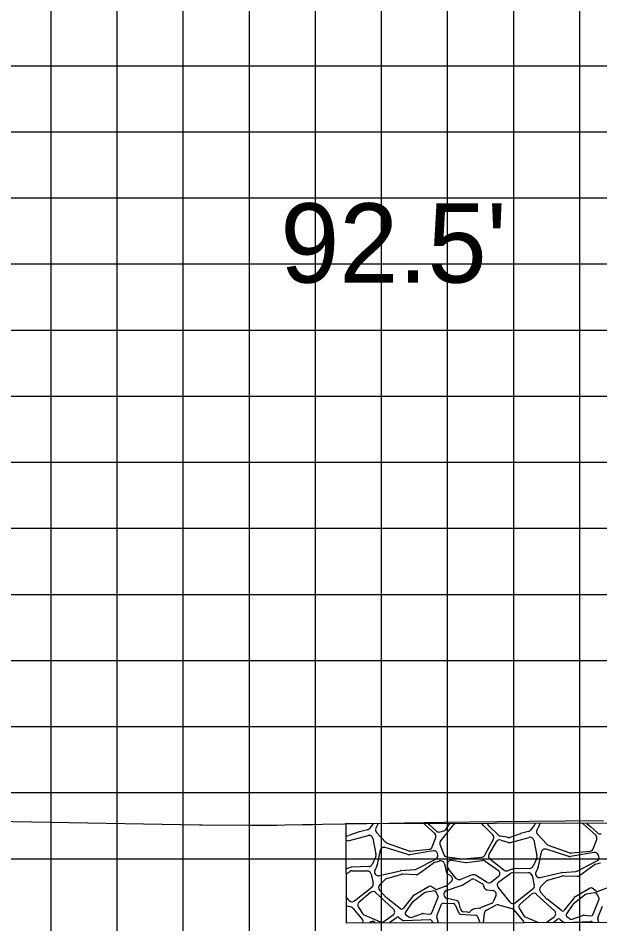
# Model space of a CAD drawing. Extents: x 1785795 to 1786139, y 442591 to 442811.
# Drawn here: x 1785863.55 to 1785872.36, y 442746.68 to 442760.39 of the extents above; entities that cross this region are included whole.
import ezdxf

# ---------------------------------------------------------------- set-up
doc = ezdxf.new("R2010")
doc.units = 0
for name, color, linetype in [('D_Roadway_SlopeLines', 7, 'Continuous'), ('D_Text_Standard', 7, 'Continuous'), ('MAJOR', 7, 'Continuous'), ('MINOR', 7, 'Continuous'), ('S_Roadway_Centerline', 7, 'Continuous')]:
    doc.layers.add(name, color=color, linetype=linetype)

msp = doc.modelspace()

# ---------------------------------------------------------------- linework, layer by layer
at = {"layer": 'D_Roadway_SlopeLines'}
for p, q in [((1785868.921, 442748.188), (1785868.869, 442748.122)), ((1785868.925, 442748.194), (1785868.921, 442748.188)), ((1785868.994, 442748.187), (1785868.967, 442748.125)), ((1785868.997, 442748.194), (1785868.994, 442748.187)), ((1785869.713, 442748.179), (1785869.695, 442748.195)), ((1785869.858, 442748.047), (1785869.713, 442748.179)), ((1785869.758, 442748.195), (1785869.777, 442748.179)), ((1785869.777, 442748.179), (1785869.884, 442748.082)), ((1785870.119, 442748.157), (1785869.945, 442747.938)), ((1785870.024, 442748.108), (1785870.07, 442748.175)), ((1785870.07, 442748.175), (1785870.085, 442748.196)), ((1785870.138, 442748.174), (1785870.129, 442748.167)), ((1785870.166, 442748.196), (1785870.138, 442748.174)), ((1785870.596, 442748.169), (1785870.569, 442748.197)), ((1785870.735, 442748.028), (1785870.596, 442748.169)), ((1785870.821, 442748.022), (1785870.675, 442748.161)), ((1785871.358, 442748.161), (1785871.306, 442748.095)), ((1785871.374, 442748.18), (1785871.358, 442748.161)), ((1785871.431, 442748.16), (1785871.404, 442748.097)), ((1785871.449, 442748.199), (1785871.431, 442748.16)), ((1785872.15, 442748.152), (1785872.097, 442748.2)), ((1785872.295, 442748.019), (1785872.15, 442748.152)), ((1785872.159, 442748.2), (1785872.214, 442748.151)), ((1785872.214, 442748.151), (1785872.322, 442748.055)), ((1785868.526, 442748.013), (1785868.512, 442748.016)), ((1785868.716, 442748.071), (1785868.555, 442748.015)), ((1785868.568, 442747.939), (1785868.848, 442748.016)), ((1785868.838, 442748.103), (1785868.72, 442748.072)), ((1785868.977, 442748.063), (1785869.116, 442747.913)), ((1785869.938, 442748.07), (1785869.993, 442748.086)), ((1785870.947, 442747.989), (1785870.85, 442748.007)), ((1785870.963, 442747.986), (1785870.947, 442747.989)), ((1785871.153, 442748.043), (1785870.992, 442747.988)), ((1785871.005, 442747.912), (1785871.285, 442747.988)), ((1785871.275, 442748.076), (1785871.157, 442748.045)), ((1785871.414, 442748.035), (1785871.553, 442747.886)), ((1785868.512, 442747.947), (1785868.537, 442747.939)), ((1785868.919, 442747.972), (1785868.968, 442747.734)), ((1785869.138, 442747.898), (1785869.464, 442747.782)), ((1785869.82, 442747.845), (1785869.873, 442747.985)), ((1785869.936, 442747.883), (1785869.993, 442747.731)), ((1785870.617, 442747.719), (1785870.745, 442747.961)), ((1785870.679, 442747.734), (1785870.791, 442747.922)), ((1785870.856, 442747.947), (1785870.946, 442747.92)), ((1785870.946, 442747.92), (1785870.974, 442747.912)), ((1785871.356, 442747.945), (1785871.405, 442747.707)), ((1785871.575, 442747.871), (1785871.901, 442747.755)), ((1785872.257, 442747.817), (1785872.31, 442747.957)), ((1785869.033, 442747.792), (1785868.987, 442747.576)), ((1785869.45, 442747.727), (1785869.106, 442747.835)), ((1785869.835, 442747.785), (1785869.477, 442747.725)), ((1785869.489, 442747.779), (1785869.773, 442747.808)), ((1785869.905, 442747.725), (1785869.899, 442747.744)), ((1785871.47, 442747.765), (1785871.425, 442747.549)), ((1785871.887, 442747.7), (1785871.543, 442747.808)), ((1785872.272, 442747.758), (1785871.914, 442747.698)), ((1785871.926, 442747.752), (1785872.21, 442747.781)), ((1785872.342, 442747.697), (1785872.337, 442747.716)), ((1785868.964, 442747.699), (1785868.909, 442747.579)), ((1785869.578, 442747.507), (1785869.875, 442747.659)), ((1785869.611, 442747.437), (1785869.832, 442747.6)), ((1785869.849, 442747.608), (1785869.93, 442747.632)), ((1785870, 442747.596), (1785870.014, 442747.554)), ((1785870.039, 442747.694), (1785870.275, 442747.664)), ((1785870.057, 442747.53), (1785870.049, 442747.575)), ((1785870.114, 442747.641), (1785870.323, 442747.608)), ((1785870.287, 442747.664), (1785870.572, 442747.689)), ((1785870.339, 442747.607), (1785870.58, 442747.638)), ((1785870.62, 442747.628), (1785870.821, 442747.487)), ((1785870.904, 442747.493), (1785870.692, 442747.66)), ((1785871.401, 442747.672), (1785871.346, 442747.552)), ((1785872.015, 442747.479), (1785872.313, 442747.632)), ((1785872.286, 442747.581), (1785872.367, 442747.605)), ((1785868.513, 442747.431), (1785868.571, 442747.472)), ((1785868.59, 442747.535), (1785868.52, 442747.511)), ((1785868.605, 442747.483), (1785868.838, 442747.481)), ((1785868.859, 442747.546), (1785868.607, 442747.538)), ((1785868.984, 442747.566), (1785868.95, 442747.487)), ((1785869.016, 442747.409), (1785869.337, 442747.484)), ((1785869.346, 442747.485), (1785869.556, 442747.501)), ((1785870.016, 442747.546), (1785870.031, 442747.469)), ((1785870.182, 442747.368), (1785870.069, 442747.503)), ((1785870.94, 442747.396), (1785871.008, 442747.445)), ((1785871.027, 442747.507), (1785870.957, 442747.484)), ((1785871.042, 442747.456), (1785871.275, 442747.453)), ((1785871.296, 442747.518), (1785871.044, 442747.51)), ((1785871.421, 442747.538), (1785871.387, 442747.459)), ((1785871.453, 442747.381), (1785871.774, 442747.457)), ((1785871.783, 442747.458), (1785871.993, 442747.473)), ((1785872.049, 442747.41), (1785872.269, 442747.572)), ((1785868.893, 442747.436), (1785868.926, 442747.289)), ((1785869.023, 442747.266), (1785869.106, 442747.351)), ((1785869.13, 442747.366), (1785869.357, 442747.432)), ((1785869.375, 442747.434), (1785869.575, 442747.426)), ((1785870.107, 442747.318), (1785870.035, 442747.254)), ((1785870.06, 442747.43), (1785870.096, 442747.411)), ((1785870.423, 442747.419), (1785870.246, 442747.351)), ((1785870.27, 442747.264), (1785870.404, 442747.348)), ((1785870.462, 442747.35), (1785870.572, 442747.29)), ((1785870.653, 442747.307), (1785870.473, 442747.414)), ((1785870.824, 442747.395), (1785870.717, 442747.312)), ((1785870.828, 442747.316), (1785870.94, 442747.396)), ((1785871.33, 442747.409), (1785871.364, 442747.261)), ((1785871.46, 442747.239), (1785871.543, 442747.324)), ((1785871.567, 442747.339), (1785871.794, 442747.405)), ((1785871.812, 442747.407), (1785872.013, 442747.399)), ((1785868.906, 442747.231), (1785868.641, 442747.025)), ((1785869.117, 442747.083), (1785869.021, 442747.188)), ((1785869.773, 442747.247), (1785869.533, 442747.105)), ((1785869.844, 442747.177), (1785869.713, 442747.155)), ((1785869.864, 442747.202), (1785869.804, 442747.245)), ((1785870.026, 442747.249), (1785869.891, 442747.198)), ((1785870.034, 442747.182), (1785870.258, 442747.258)), ((1785870.602, 442747.246), (1785870.602, 442747.242)), ((1785870.652, 442747.192), (1785870.737, 442747.182)), ((1785870.937, 442747.084), (1785870.816, 442747.234)), ((1785871.343, 442747.203), (1785871.078, 442746.998)), ((1785872.21, 442747.22), (1785871.97, 442747.077)), ((1785872.301, 442747.174), (1785872.241, 442747.218)), ((1785872.463, 442747.221), (1785872.328, 442747.171)), ((1785868.561, 442747.035), (1785868.514, 442747.094)), ((1785868.886, 442747.155), (1785868.712, 442747.007)), ((1785869.233, 442746.903), (1785868.961, 442747.154)), ((1785869.34, 442746.907), (1785869.12, 442747.079)), ((1785869.525, 442747.098), (1785869.38, 442746.912)), ((1785869.7, 442747.149), (1785869.515, 442747.004)), ((1785869.814, 442746.845), (1785869.908, 442747.082)), ((1785869.906, 442747.106), (1785869.873, 442747.163)), ((1785869.999, 442747.107), (1785869.997, 442747.116)), ((1785870.185, 442747.033), (1785870.043, 442747.064)), ((1785870.782, 442747.102), (1785870.743, 442747.015)), ((1785870.998, 442747.008), (1785870.937, 442747.084)), ((1785871.323, 442747.128), (1785871.149, 442746.979)), ((1785871.67, 442746.876), (1785871.399, 442747.126)), ((1785871.554, 442747.055), (1785871.458, 442747.161)), ((1785871.777, 442746.88), (1785871.557, 442747.052)), ((1785871.963, 442747.07), (1785871.817, 442746.885)), ((1785872.137, 442747.122), (1785871.952, 442746.977)), ((1785872.281, 442747.149), (1785872.15, 442747.127)), ((1785872.251, 442746.818), (1785872.345, 442747.054)), ((1785872.343, 442747.079), (1785872.31, 442747.136)), ((1785868.514, 442746.958), (1785868.587, 442746.938)), ((1785868.616, 442746.919), (1785868.762, 442746.741)), ((1785868.701, 442746.933), (1785868.762, 442746.836)), ((1785869.509, 442746.998), (1785869.413, 442746.856)), ((1785869.888, 442746.799), (1785869.961, 442746.975)), ((1785869.988, 442746.992), (1785870.143, 442746.985)), ((1785870.167, 442746.968), (1785870.221, 442746.842)), ((1785870.245, 442746.908), (1785870.228, 442746.989)), ((1785870.43, 442746.895), (1785870.398, 442746.869)), ((1785870.536, 442746.916), (1785870.46, 442746.908)), ((1785870.712, 442746.985), (1785870.551, 442746.92)), ((1785870.64, 442746.887), (1785870.783, 442746.961)), ((1785870.824, 442746.965), (1785870.935, 442746.935)), ((1785870.935, 442746.935), (1785871.024, 442746.91)), ((1785871.053, 442746.891), (1785871.199, 442746.713)), ((1785871.138, 442746.906), (1785871.2, 442746.809)), ((1785871.947, 442746.97), (1785871.85, 442746.829)), ((1785872.325, 442746.771), (1785872.398, 442746.947)), ((1785868.788, 442746.814), (1785869.031, 442746.708)), ((1785869.088, 442746.714), (1785869.227, 442746.815)), ((1785869.18, 442746.704), (1785869.279, 442746.778)), ((1785869.314, 442746.778), (1785869.37, 442746.734)), ((1785869.42, 442746.816), (1785869.475, 442746.779)), ((1785869.501, 442746.775), (1785869.671, 442746.837)), ((1785869.684, 442746.838), (1785869.784, 442746.827)), ((1785869.912, 442746.696), (1785869.887, 442746.78)), ((1785870.245, 442746.825), (1785870.481, 442746.809)), ((1785870.355, 442746.856), (1785870.295, 442746.862)), ((1785870.505, 442746.791), (1785870.535, 442746.716)), ((1785870.595, 442746.697), (1785870.61, 442746.842)), ((1785871.225, 442746.787), (1785871.426, 442746.699)), ((1785871.542, 442746.699), (1785871.664, 442746.788)), ((1785871.857, 442746.789), (1785871.913, 442746.751)), ((1785871.938, 442746.748), (1785872.108, 442746.809)), ((1785872.121, 442746.811), (1785872.221, 442746.8)), ((1785868.871, 442746.697), (1785868.867, 442746.693)), ((1785868.958, 442746.694), (1785868.947, 442746.703)), ((1785869.389, 442746.728), (1785869.783, 442746.744)), ((1785869.809, 442746.729), (1785869.828, 442746.695)), ((1785871.648, 442746.699), (1785871.717, 442746.751)), ((1785871.751, 442746.75), (1785871.807, 442746.707)), ((1785871.826, 442746.7), (1785872.22, 442746.717)), ((1785872.246, 442746.702), (1785872.247, 442746.701)), ((1785872.339, 442746.701), (1785872.324, 442746.752))]:
    msp.add_line(p, q, dxfattribs=at)
msp.add_lwpolyline([(1785882.012, 442748.221), (1785868.512, 442748.193), (1785868.515, 442746.693), (1785882.012, 442746.721)], dxfattribs=at)
for centre, radius, start, end in [((1785869.019, 442748.101), 0.057, 156.0031, 222.9319), ((1785870.164, 442748.122), 0.057, 128.0185, 141.583), ((1785870.714, 442748.202), 0.057, 184.7726, 215.9404), ((1785870.714, 442748.202), 0.057, 215.9404, 226.4797), ((1785871.329, 442748.216), 0.057, 321.3116, 342.8512), ((1785868.536, 442748.069), 0.057, 259.4928, 289.0125), ((1785868.734, 442748.017), 0.057, 104.6138, 109.0125), ((1785868.824, 442748.158), 0.057, 284.6138, 321.3116), ((1785868.863, 442747.961), 0.057, 11.7661, 105.304), ((1785869.819, 442748.005), 0.057, 339.4382, 47.5999), ((1785869.922, 442748.125), 0.057, 228.2524, 286.2171), ((1785869.977, 442748.141), 0.057, 286.2171, 325.1429), ((1785870.694, 442747.988), 0.057, 332.3278, 44.3587), ((1785870.86, 442748.063), 0.057, 226.4797, 259.4928), ((1785870.973, 442748.042), 0.057, 259.4928, 289.0125), ((1785871.171, 442747.99), 0.057, 104.6138, 109.0125), ((1785871.261, 442748.131), 0.057, 284.6138, 321.3116), ((1785871.3, 442747.933), 0.057, 11.7661, 105.304), ((1785871.456, 442748.074), 0.057, 156.0031, 222.9319), ((1785872.256, 442747.977), 0.057, 339.4382, 47.5999), ((1785872.359, 442748.098), 0.057, 228.2524, 286.2171), ((1785868.553, 442747.994), 0.057, 253.4133, 285.304), ((1785869.158, 442747.952), 0.057, 222.9319, 250.2948), ((1785869.99, 442747.903), 0.057, 141.583, 200.2832), ((1785870.84, 442747.893), 0.057, 73.4133, 149.1851), ((1785870.99, 442747.967), 0.057, 253.4133, 285.304), ((1785871.595, 442747.925), 0.057, 222.9319, 250.2948), ((1785868.912, 442747.723), 0.057, 335.3962, 11.7661), ((1785869.089, 442747.78), 0.057, 72.6256, 168.0653), ((1785869.467, 442747.781), 0.057, 252.6256, 279.5129), ((1785869.483, 442747.836), 0.057, 250.2948, 275.8831), ((1785869.767, 442747.865), 0.057, 275.8831, 339.4382), ((1785869.844, 442747.729), 0.057, 14.8828, 99.5129), ((1785869.849, 442747.71), 0.057, 297.1601, 14.8828), ((1785870.046, 442747.75), 0.057, 200.2832, 262.8756), ((1785870.567, 442747.745), 0.057, 274.958, 332.3278), ((1785870.728, 442747.705), 0.057, 149.1851, 231.6644), ((1785871.526, 442747.753), 0.057, 72.6256, 168.0653), ((1785871.92, 442747.808), 0.057, 250.2948, 275.8831), ((1785872.204, 442747.837), 0.057, 275.8831, 339.4382), ((1785872.281, 442747.702), 0.057, 14.8828, 99.5129), ((1785868.857, 442747.603), 0.057, 271.7953, 335.3962), ((1785868.932, 442747.588), 0.057, 336.8362, 348.0653), ((1785869.866, 442747.554), 0.057, 106.6402, 126.3474), ((1785869.946, 442747.578), 0.057, 18.8953, 106.6402), ((1785870.105, 442747.585), 0.057, 80.8875, 189.6635), ((1785870.282, 442747.721), 0.057, 262.8756, 274.958), ((1785870.332, 442747.664), 0.057, 260.8875, 277.3021), ((1785870.588, 442747.582), 0.057, 54.7961, 97.3021), ((1785871.349, 442747.695), 0.057, 335.3962, 11.7661), ((1785871.904, 442747.754), 0.057, 252.6256, 279.5129), ((1785872.303, 442747.526), 0.057, 106.6401, 126.3474), ((1785872.287, 442747.683), 0.057, 297.1601, 14.8828), ((1785868.502, 442747.565), 0.057, 281.282, 288.7987), ((1785868.604, 442747.426), 0.057, 89.4474, 125.5779), ((1785868.609, 442747.481), 0.057, 91.7953, 108.7987), ((1785868.837, 442747.424), 0.057, 12.9406, 89.4474), ((1785869.003, 442747.464), 0.057, 156.8362, 283.2181), ((1785869.35, 442747.429), 0.057, 94.1223, 103.2181), ((1785869.552, 442747.557), 0.057, 274.1223, 297.1601), ((1785869.96, 442747.535), 0.057, 10.9923, 18.8953), ((1785870.087, 442747.48), 0.057, 190.9923, 241.7127), ((1785870.113, 442747.54), 0.057, 189.6635, 219.9599), ((1785870.788, 442747.44), 0.057, 308.2431, 54.7961), ((1785870.939, 442747.538), 0.057, 231.6644, 272.0374), ((1785870.939, 442747.538), 0.057, 272.0374, 288.7987), ((1785871.042, 442747.399), 0.057, 89.4474, 125.5779), ((1785871.046, 442747.453), 0.057, 91.7953, 108.7987), ((1785871.274, 442747.396), 0.057, 12.9406, 89.4474), ((1785871.294, 442747.575), 0.057, 271.7953, 335.3962), ((1785871.44, 442747.437), 0.057, 156.8362, 283.2181), ((1785871.369, 442747.561), 0.057, 336.8362, 348.0653), ((1785871.787, 442747.401), 0.057, 94.1223, 103.2181), ((1785871.989, 442747.53), 0.057, 274.1223, 297.1601), ((1785869.146, 442747.311), 0.057, 106.2573, 135.7226), ((1785869.373, 442747.377), 0.057, 87.7893, 106.2573), ((1785869.578, 442747.483), 0.057, 267.7893, 306.3474), ((1785870.069, 442747.36), 0.057, 311.5659, 61.7127), ((1785870.226, 442747.405), 0.057, 219.9599, 290.8996), ((1785870.434, 442747.3), 0.057, 61.5111, 122.0392), ((1785870.443, 442747.365), 0.057, 59.2901, 110.8996), ((1785870.682, 442747.356), 0.057, 239.2901, 308.2431), ((1785870.861, 442747.269), 0.057, 125.5779, 218.8298), ((1785871.583, 442747.284), 0.057, 106.2573, 135.7226), ((1785871.81, 442747.35), 0.057, 87.7893, 106.2573), ((1785872.015, 442747.456), 0.057, 267.7893, 306.3474), ((1785868.923, 442747.112), 0.057, 47.2362, 130.6049), ((1785868.871, 442747.276), 0.057, 307.7317, 12.9406), ((1785869.064, 442747.226), 0.057, 135.7226, 222.1477), ((1785869.787, 442747.222), 0.0285, 53.821, 120.7317), ((1785869.849, 442747.149), 0.0285, 30.0093, 99.5626), ((1785869.881, 442747.225), 0.0285, 233.821, 290.5527), ((1785870.053, 442747.129), 0.057, 108.7646, 192.4927), ((1785870.016, 442747.275), 0.0285, 290.5527, 311.5659), ((1785870.24, 442747.312), 0.057, 288.7646, 302.0392), ((1785870.545, 442747.24), 0.057, 6.2014, 61.5111), ((1785870.659, 442747.248), 0.057, 186.2014, 263.3045), ((1785870.73, 442747.125), 0.057, 335.6766, 83.3045), ((1785871.308, 442747.248), 0.057, 307.7317, 12.9406), ((1785871.501, 442747.199), 0.057, 135.7226, 222.1477), ((1785872.224, 442747.195), 0.0285, 53.821, 120.7317), ((1785872.318, 442747.197), 0.0285, 233.821, 290.5527), ((1785868.606, 442747.071), 0.057, 218.8298, 307.7317), ((1785869.138, 442747.102), 0.0285, 222.1477, 231.9533), ((1785869.548, 442747.08), 0.0285, 120.7317, 141.9533), ((1785869.718, 442747.127), 0.0285, 99.5626, 128.1328), ((1785869.881, 442747.092), 0.0285, 338.3658, 30.0093), ((1785870.055, 442747.119), 0.057, 192.4927, 257.725), ((1785870.172, 442746.977), 0.057, 11.7661, 77.725), ((1785871.36, 442747.085), 0.057, 47.2362, 130.6049), ((1785871.575, 442747.075), 0.0285, 222.1477, 231.9533), ((1785871.985, 442747.053), 0.0285, 120.7317, 141.9533), ((1785872.155, 442747.099), 0.0285, 99.5626, 128.1328), ((1785872.286, 442747.121), 0.0285, 30.0093, 99.5626), ((1785872.318, 442747.065), 0.0285, 338.3658, 30.0093), ((1785868.572, 442746.883), 0.057, 39.3162, 74.6151), ((1785868.749, 442746.963), 0.057, 130.6049, 212.3212), ((1785869.194, 442746.861), 0.057, 305.9657, 47.2362), ((1785869.358, 442746.93), 0.0285, 231.9533, 321.9533), ((1785869.533, 442746.982), 0.0285, 128.1328, 145.6686), ((1785869.987, 442746.964), 0.0285, 87.4808, 157.5572), ((1785870.141, 442746.957), 0.0285, 23.1081, 87.4808), ((1785870.301, 442746.919), 0.057, 191.7661, 263.6481), ((1785870.466, 442746.851), 0.057, 96.4837, 129.7232), ((1785870.53, 442746.973), 0.057, 276.4837, 291.9785), ((1785870.691, 442747.038), 0.057, 291.9785, 335.6766), ((1785870.809, 442746.91), 0.057, 74.6151, 117.4311), ((1785871.043, 442747.043), 0.057, 218.8298, 307.7317), ((1785871.009, 442746.855), 0.057, 39.3162, 74.6151), ((1785871.187, 442746.936), 0.057, 130.6049, 212.3212), ((1785871.97, 442746.954), 0.0285, 128.1328, 145.6686), ((1785868.811, 442746.867), 0.057, 212.3212, 246.3365), ((1785869.297, 442746.755), 0.0285, 51.7901, 126.8935), ((1785869.436, 442746.84), 0.0285, 145.6686, 235.6686), ((1785869.492, 442746.802), 0.0285, 235.6686, 289.8421), ((1785869.68, 442746.81), 0.0285, 83.7865, 109.8421), ((1785869.787, 442746.856), 0.0285, 263.7865, 338.3658), ((1785869.914, 442746.788), 0.0285, 157.5572, 196.2862), ((1785870.247, 442746.854), 0.0285, 203.1081, 266.0312), ((1785870.362, 442746.912), 0.057, 263.6481, 309.7232), ((1785870.479, 442746.78), 0.0285, 21.9785, 86.0312), ((1785870.666, 442746.836), 0.057, 117.4311, 174.1642), ((1785871.248, 442746.839), 0.057, 212.3212, 246.3365), ((1785871.631, 442746.834), 0.057, 305.9657, 47.2362), ((1785871.734, 442746.728), 0.0285, 51.7901, 126.8935), ((1785871.795, 442746.902), 0.0285, 231.9533, 321.9533), ((1785871.873, 442746.813), 0.0285, 145.6686, 235.6686), ((1785872.118, 442746.783), 0.0285, 83.7865, 109.8421), ((1785872.225, 442746.828), 0.0285, 263.7865, 338.3658), ((1785872.352, 442746.76), 0.0285, 157.5572, 196.2862), ((1785868.717, 442746.705), 0.057, 348.5243, 39.3162), ((1785868.912, 442746.658), 0.057, 51.9953, 135.7907), ((1785869.054, 442746.76), 0.057, 246.3365, 305.9657), ((1785869.197, 442746.681), 0.0285, 126.8935, 152.1381), ((1785869.388, 442746.756), 0.0285, 231.7901, 272.349), ((1785869.784, 442746.715), 0.0285, 29.1506, 92.349), ((1785870.509, 442746.706), 0.0285, 342.2238, 21.9785), ((1785871.155, 442746.677), 0.057, 21.765, 39.3162), ((1785871.825, 442746.729), 0.0285, 231.7901, 272.349), ((1785871.929, 442746.775), 0.0285, 235.6686, 289.8421), ((1785872.221, 442746.688), 0.0285, 29.1506, 92.349)]:
    msp.add_arc(centre, radius, start, end, dxfattribs=at)
at = {"layer": 'MAJOR'}
for p, q in [((1785871.052, 442738.665), (1785871.052, 442783.665)), ((1785821.052, 442758.665), (1786101.052, 442758.665)), ((1785821.052, 442753.665), (1786101.052, 442753.665)), ((1785821.052, 442748.665), (1786101.052, 442748.665))]:
    msp.add_line(p, q, dxfattribs=at)
at = {"layer": 'MINOR'}
for p, q in [((1785864.052, 442738.665), (1785864.052, 442783.665)), ((1785865.052, 442738.665), (1785865.052, 442783.665)), ((1785866.052, 442738.665), (1785866.052, 442783.665)), ((1785867.052, 442738.665), (1785867.052, 442783.665)), ((1785868.052, 442738.665), (1785868.052, 442783.665)), ((1785869.052, 442738.665), (1785869.052, 442783.665)), ((1785870.052, 442738.665), (1785870.052, 442783.665)), ((1785872.052, 442738.665), (1785872.052, 442783.665)), ((1785821.052, 442759.665), (1786101.052, 442759.665)), ((1785821.052, 442757.665), (1786101.052, 442757.665)), ((1785821.052, 442756.665), (1786101.052, 442756.665)), ((1785821.052, 442755.665), (1786101.052, 442755.665)), ((1785821.052, 442754.665), (1786101.052, 442754.665)), ((1785821.052, 442752.665), (1786101.052, 442752.665)), ((1785821.052, 442751.665), (1786101.052, 442751.665)), ((1785821.052, 442750.665), (1786101.052, 442750.665)), ((1785821.052, 442749.665), (1786101.052, 442749.665)), ((1785821.052, 442747.665), (1786101.052, 442747.665))]:
    msp.add_line(p, q, dxfattribs=at)
at = {"layer": 'S_Roadway_Centerline'}
msp.add_lwpolyline([(1785860.082, 442748.287), (1785866.297, 442748.179), (1785866.338, 442748.18), (1785867.036, 442748.174), (1785867.085, 442748.173), (1785867.136, 442748.172), (1785867.186, 442748.172), (1785867.267, 442748.173), (1785867.361, 442748.174), (1785867.469, 442748.175), (1785867.589, 442748.177), (1785867.858, 442748.181), (1785868.005, 442748.184), (1785868.157, 442748.187), (1785869.162, 442748.203), (1785869.402, 442748.207), (1785870.004, 442748.217), (1785870.378, 442748.222), (1785870.806, 442748.228), (1785871.292, 442748.234), (1785871.831, 442748.24), (1785872.411, 442748.245)], dxfattribs=at)

# ---------------------------------------------------------------- texts
at = {"layer": 'D_Text_Standard'}
msp.add_text("92.5'", height=1.2, dxfattribs=at).set_placement((1785867.52, 442756.383))

doc.saveas('drawing.dxf')
